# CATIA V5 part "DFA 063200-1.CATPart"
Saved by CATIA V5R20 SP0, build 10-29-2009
Part number: DFA 063200-1
Revision: ANY
Definition: UNKNOWN
Nomenclature: DFA 063200-1
Source: Unknown
Bounding box of the stored display mesh (mm): x -2.5 to 2.5, y 0.15 to 2.5, z -2.5 to 2.5
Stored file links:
  C:\Users\Utente\Desktop\IO LAVORO\3D X SITO CF\CUMSA\3D files FA\FA 063205-21\DFA 063200-1.CATPart

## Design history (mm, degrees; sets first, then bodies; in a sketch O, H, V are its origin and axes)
Body1 "Cortar-Extruir1" (main body)
  Solid1: solid without history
